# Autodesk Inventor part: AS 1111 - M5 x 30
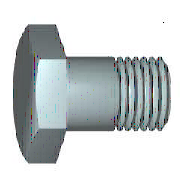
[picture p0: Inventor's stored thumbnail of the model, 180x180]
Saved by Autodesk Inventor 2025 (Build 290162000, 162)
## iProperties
Created: 2024-01
Part Number: AS 1111 - M5 x 30
Material: Acciaio, Dolce
Description: Bulloni e viti commerciali esagonali metrici ISO
Document SubType Name: Modeling
Standard: AS 1111
Designer: R5800u
Standards Organization: AS
Language: it-IT
Size Designation: M5 x 30
Categories: <MemberInstance><Categories><Category DisplayName="Elementi di fissaggio" InternalName="e4da775c-781d-43d5-af7c-5136215cf5a6" Mnemonic="FSTN"><Category DisplayN
Density: 7.85 g/cm^3
Appearance: Semilucidato
IsCustomPart: 0
Author: R5800u
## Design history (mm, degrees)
body "Solid1"
workplane "Work Plane1"
revolve "Corpo" stored, may be unused: angle "d12" = 90 deg
sketch "Schizzo2"
  geometry: L1 (0, 4.619)-(4, 2.309); L2 (4, 2.309)-(4, -2.309); L3 (4, -2.309)-(0, -4.619); L4 (0, -4.619)-(-4, -2.309); L5 (-4, -2.309)-(-4, 2.309); L6 (-4, 2.309)-(0, 4.619); 2 further points
  constraints: 12 end point, 1 coincident, 1 vertical, 11 other
  dimensions: "d11" = 8 distance between parallel lines of L5 L2 (= SW)
extrude "Testa" join sketch "Schizzo2" distance "d3" = 3.38 (= KOH - SD); taper "d4" = 0 deg
revolve "Smusso1" stored, may be unused: angle "d21" = 90 deg
feature "Filettatura" dims "d15" = 16 (= GEL), "d16" = 0
chamfer "Smusso2" distance "d6" = 0.49076 (= -0.5 x SPD + 0.5 x GD); stored, may be unused: second distance "d7" = 0.49086 (computed from GUL), angle "d55" = 45 deg
sketch "Schizzo1"
  geometry: L1 (0, 4)-(0, 2.5); L2 (14, 2.5)-(30, 2.5); L3 (30, 2.5)-(30, 0); L4 (30, 0)-(-0.5, 0); L5 (-6.6, 0)-(36.1, 0) reference; L6 (-0.5, 0)-(-0.5, 4); L7 (-0.5, 4)-(0, 4); L8 (14, 2.5)-(13.509, 2.5); L9 (13.509, 2.5)-(0, 2.5); L10 (0, -0.8)-(0, 4.8) reference
  constraints: 16 end point, 2 collinear, 2 perpendicular, 1 parallel
  dimensions: "d0" = 30 distance between parallel lines of L3 L1 (= NLG); "d1" = 16 distance from line of L2.start L3 (= GEL); "d2" = 5 diameter of L2 L4 (= GD); "d9" = 0.5001 distance between parallel lines of L6 L1 (computed from SD); "d10" = 8 diameter of L7 L4 (= SD2); "d13" = 0.49086 distance of L2.start L8.end (computed from GAL); "d14" = 5 diameter of L9 L4 (= BDM)
sketch "Schizzo4"
  geometry: L1 (-3.88, 4)-(-3.88, 4.619); L2 (-3.88, 4.619)-(-3.523, 4.619); L3 (-3.523, 4.619)-(-3.88, 4); L4 (-4.556, 0)-(0.176, 0) reference; L5 (-0.5, 4.619)-(-3.88, 4.619) reference; L6 (-3.88, 2.309)-(-3.88, 4.619) reference
  constraints: 6 end point, 2 collinear, 1 perpendicular, 1 vertical
  dimensions: "d5" = 30 deg angle of L3 L1 (= ANG1); "d19" = 8 diameter of L1.start L4 (= SW0)
other parameters: "NLG" = 30 [user parameter; used in 1 equation term], "GD" = 5 (= NND) [user parameter; used in 2 equation terms], "BDM" = 5 (= NND) [user parameter; used in 1 equation term], "KOH" = 3.88 [user parameter; used in 1 equation term], "GEL" = 16 [user parameter; used in 2 equation terms], "SW" = 8 [user parameter; used in 5 equation terms], "SW0" = 8 (= SW) [user parameter; used in 1 equation term], "SPD" = 4.01848 (= NND - 1.2269 x PTC) [user parameter; used in 1 equation term], "SD2" = 8 (= SW) [user parameter; used in 1 equation term], "SD" = 0.5 [user parameter; used in 3 equation terms], "ANG1" = 30 deg [user parameter; used in 1 equation term], "GAL" = 0.49076 (= 0.61345 x PTC) [user parameter; used in 1 equation term], "GUL" = 0.49076 (= 0.61345 x PTC) [user parameter; used in 1 equation term], "d8" = 0, "RR" = 0.2 [user parameter], "d57" = 0, "d58" = 0, "TPU" = 12.5 (computed from PTC) [user parameter], "WFT" = 0.5 (= SD) [user parameter], "GD1" = 4.01848 (= THREADDIA - 1.2269 x PTC) [user parameter], "THREADDIA" = 5 [user parameter; used in 1 equation term], "SDH" = 8 (= SW) [user parameter], "TOA" = 30 deg [user parameter], "FAWI" = 45 deg [user parameter], "PTC" = 0.8 [user parameter; used in 5 equation terms], "NND" = 5 [user parameter; used in 3 equation terms], "E0" = 9.24 (= 1.155 x SW) [user parameter]
